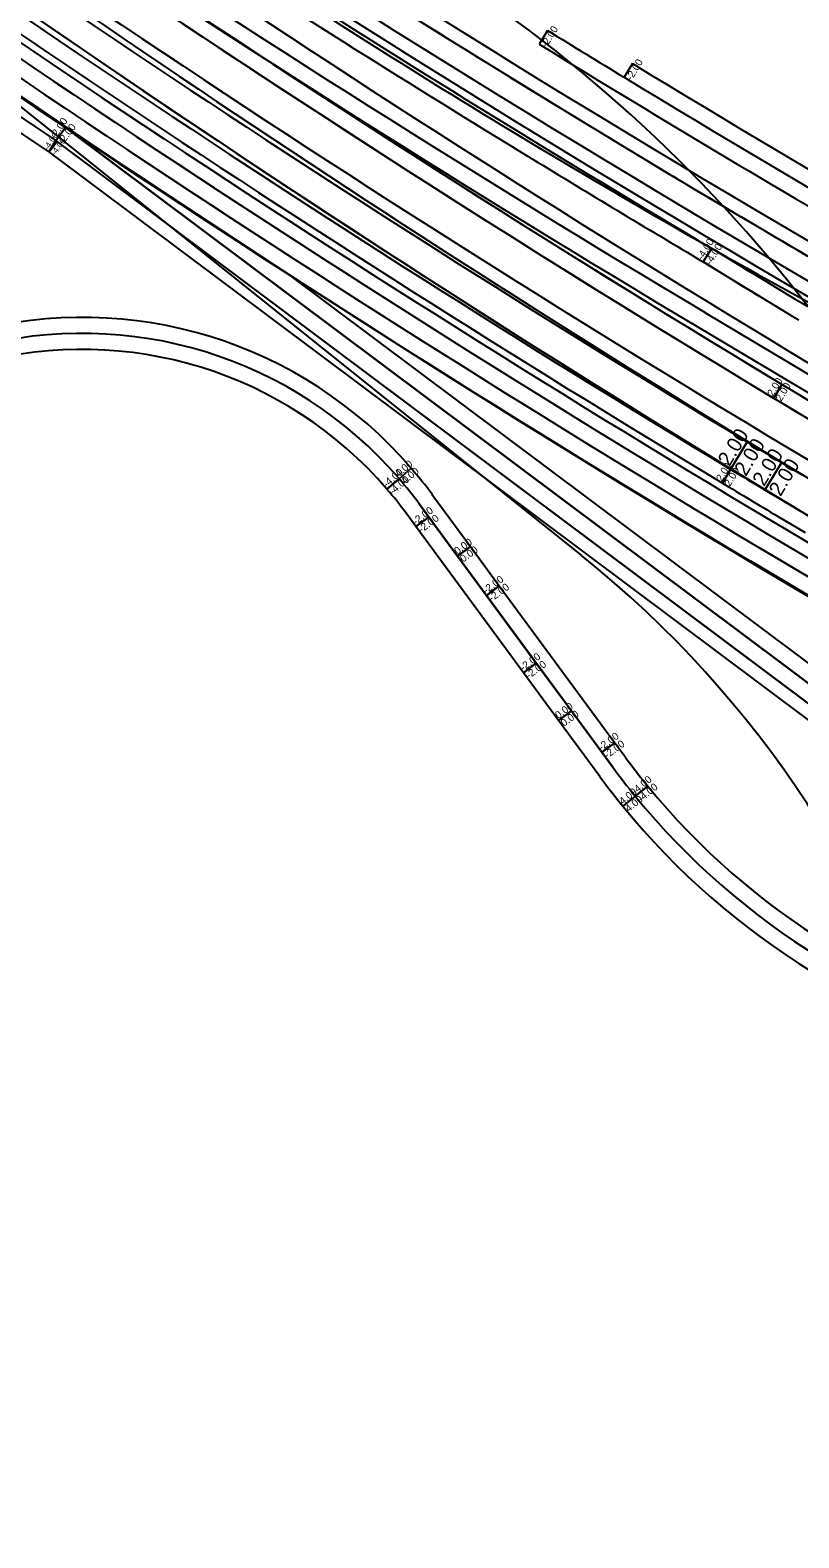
# Model space of a CAD drawing. Extents: x 2342222 to 2351711, y 366548 to 372860.
# Drawn here: x 2345691 to 2346266, y 369068 to 370197 of the extents above; entities that cross this region are included whole.
import ezdxf

# ---------------------------------------------------------------- set-up
doc = ezdxf.new("R2010")
doc.units = 0
for name, color, linetype in [('RD_HC_Cl', 7, 'Continuous'), ('RD_PD_Final_LnLine', 7, 'Continuous'), ('RD_PD_PaveShd', 7, 'Continuous'), ('RD_PD_SuperShp_BL_EB_526', 7, 'Continuous'), ('RD_PD_SuperShp_BL_WB_526', 7, 'Continuous'), ('RD_PD_SuperShp_EB_526', 7, 'Continuous'), ('RD_PD_SuperShp_LINE-A', 7, 'Continuous'), ('RD_PD_SuperShp_Line-B', 7, 'Continuous'), ('RD_PD_SuperShp_REL_L-2118', 7, 'Continuous'), ('RD_PD_SuperShp_REL_L-2523', 7, 'Continuous'), ('RD_PD_SuperShp_REL_LINE-3', 7, 'Continuous'), ('RD_PD_SuperShp_WB_526', 7, 'Continuous')]:
    doc.layers.add(name, color=color, linetype=linetype)

msp = doc.modelspace()

# ---------------------------------------------------------------- linework, layer by layer
at = {"layer": 'RD_HC_Cl'}
msp.add_line((2345614.6, 370194.7), (2346103.4, 369803.5), dxfattribs=at)
msp.add_line((2345614.6, 370194.7), (2346103.4, 369803.5), dxfattribs=at)
for centre, radius, start, end in [((2349158.4, 375253.9), 6000, 236.19528, 241.60251), ((2349158.4, 375253.9), 6000, 236.19528, 241.60251), ((2345401.1, 369318.9), 1100, 337.175, 58.1352), ((2345401.1, 369318.9), 1100, 337.175, 58.1352), ((2345603.4, 369178.9), 800, 339.7746, 51.3248), ((2345603.4, 369178.9), 800, 339.7746, 51.3248)]:
    msp.add_arc(centre, radius, start, end, dxfattribs=at)
at = {"layer": 'RD_PD_Final_LnLine'}
msp.add_line((2346236.7, 369794.6), (2347945.2, 368775.3), dxfattribs=at)
msp.add_line((2346236.7, 369794.6), (2347945.2, 368775.3), dxfattribs=at)
msp.add_arc((2351872.8, 379241), 11000, 231.26372, 239.17851, dxfattribs=at)
msp.add_arc((2351872.8, 379241), 11000, 231.26372, 239.17851, dxfattribs=at)
at = {"layer": 'RD_PD_PaveShd'}
for centre, radius, start, end in [((2352152.8, 379726.2), 11446, 233.26372, 239.17851), ((2352002, 379817.2), 11374.2, 235.48286, 239.33461), ((2352152.8, 379726.2), 11374.2, 238.44698, 238.8683), ((2352152.8, 379726.2), 11386.2, 238.44699, 238.8683)]:
    msp.add_arc(centre, radius, start, end, dxfattribs=at)
at = {"layer": 'RD_PD_SuperShp_BL_EB_526'}
for p, q in [((2346227.5, 369888.5), (2346215.1, 369867.9)), ((2346215.1, 369867.9), (2346227.5, 369888.5)), ((2346215.1, 369867.9), (2346208.9, 369857.7)), ((2346208.9, 369857.7), (2346215.1, 369867.9)), ((2346277, 369830.9), (2346256.4, 369843.2)), ((2346277, 369830.9), (2346256.4, 369843.2)), ((2346250.2, 369832.9), (2346270.8, 369820.6))]:
    msp.add_line(p, q, dxfattribs=at)
for radius, start, end in [(11472.3, 233.26372, 239.17851), (11484.3, 233.50318, 238.93904), (11484.3, 233.50318, 238.93904), (11508.3, 233.50318, 238.93904), (11508.3, 233.50318, 238.93904), (11520.3, 233.50318, 238.93904), (11484.3, 238.93904, 239.17851), (11484.3, 238.93904, 239.17851), (11508.3, 238.93904, 239.17851), (11508.3, 238.93904, 239.17851), (11520.3, 238.93904, 239.17851)]:
    msp.add_arc((2352152.8, 379726.2), radius, start, end, dxfattribs=at)
at = {"layer": 'RD_PD_SuperShp_BL_WB_526'}
for p, q in [((2346200.9, 370033.6), (2346194.6, 370023.4)), ((2346194.6, 370023.4), (2346200.9, 370033.6)), ((2346247.3, 369921.3), (2346253.5, 369931.6)), ((2346253.5, 369931.6), (2346247.3, 369921.3))]:
    msp.add_line(p, q, dxfattribs=at)
for centre, radius, start, end in [((2352152.8, 379726.2), 11410, 233.26372, 239.17851), ((2352152.8, 379726.2), 11434, 233.26372, 239.17851), ((2352152.8, 379726.2), 11434, 233.50319, 238.93903), ((2352152.8, 379726.2), 11446, 233.50319, 238.93903), ((2352002, 379817.2), 11374.2, 235.48286, 239.33461), ((2352002, 379817.2), 11386.2, 235.48286, 238.5668), ((2352002, 379817.2), 11386.2, 238.5668, 238.58075), ((2352002, 379817.2), 11386.2, 238.58075, 239.33369), ((2352152.8, 379726.2), 11374.2, 238.44699, 238.8683), ((2352152.8, 379726.2), 11386.2, 238.44699, 238.44792), ((2352152.8, 379726.2), 11386.2, 238.44792, 238.8683), ((2352152.8, 379726.2), 11434, 238.93903, 239.17851), ((2352152.8, 379726.2), 11446, 238.93903, 239.17851)]:
    msp.add_arc(centre, radius, start, end, dxfattribs=at)
at = {"layer": 'RD_PD_SuperShp_EB_526'}
for p, q in [((2346241, 369852.8), (2346253.3, 369873.4)), ((2346253.3, 369873.4), (2346241, 369852.8))]:
    msp.add_line(p, q, dxfattribs=at)
for radius, start, end in [(11459.2, 233.34382, 238.69829), (11483.2, 233.26372, 239.17851), (11483.2, 233.34465, 238.6991), (11459.2, 238.69829, 239.17851), (11483.2, 238.6991, 239.17851)]:
    msp.add_arc((2352206.9, 379664.6), radius, start, end, dxfattribs=at)
at = {"layer": 'RD_PD_SuperShp_LINE-A'}
for radius, start, end in [(11400.7, 232.99132, 239.10724), (11390.7, 232.99132, 240.43629), (11416.7, 232.99132, 240.43659), (11416.7, 232.99132, 240.43659), (11426.7, 232.99132, 240.43659), (11400.7, 237.52398, 238.02654), (11400.7, 238.02654, 238.52911), (11400.7, 238.52911, 239.03167), (11400.7, 239.03167, 239.10724), (11400.7, 239.10724, 240.43629), (11400.7, 239.10724, 239.53424), (11400.7, 239.53424, 240.0368)]:
    msp.add_arc((2352034, 379865.6), radius, start, end, dxfattribs=at)
at = {"layer": 'RD_PD_SuperShp_Line-B'}
for p, q in [((2345709.9, 370114.3), (2345717.1, 370123.9)), ((2345717.1, 370123.9), (2346489.7, 369545.7)), ((2345717.1, 370123.9), (2345882.8, 370014.8)), ((2346489.7, 369545.7), (2345717.1, 370123.9)), ((2345710.9, 370113.5), (2345704.9, 370105.5)), ((2345704.9, 370105.5), (2346273.6, 369679.9)), ((2346482.5, 369536.1), (2345709.9, 370114.3)), ((2346279.6, 369687.9), (2345710.9, 370113.5))]:
    msp.add_line(p, q, dxfattribs=at)
msp.add_lwpolyline([(2345882.8, 370014.8), (2346496.9, 369555.3)], dxfattribs=at)
at = {"layer": 'RD_PD_SuperShp_REL_L-2118'}
for p, q in [((2345976, 369868.8), (2345966.9, 369861)), ((2345966.9, 369861), (2345976, 369868.8)), ((2345966.9, 369861), (2345957.8, 369853.1)), ((2345957.8, 369853.1), (2345966.9, 369861)), ((2345991.5, 369849.3), (2346020.4, 369810.1)), ((2345979.5, 369825.1), (2345972.2, 369835.1)), ((2346010.7, 369802.9), (2345981.9, 369842.2)), ((2345981.9, 369842.2), (2345989.2, 369832.2)), ((2345989.2, 369832.2), (2345979.5, 369825.1)), ((2345979.5, 369825.1), (2345989.2, 369832.2)), ((2346060, 369715.7), (2345979.5, 369825.1)), ((2345989.2, 369832.2), (2346069.6, 369722.8)), ((2346020.4, 369810.1), (2346010.7, 369802.9)), ((2346010.7, 369802.9), (2346020.4, 369810.1)), ((2346032.3, 369773.6), (2346010.7, 369802.9)), ((2346020.4, 369810.1), (2346041.9, 369780.8)), ((2346041.9, 369780.8), (2346032.3, 369773.6)), ((2346032.3, 369773.6), (2346041.9, 369780.8)), ((2346041.9, 369780.8), (2346128.3, 369663.3)), ((2346118.6, 369656.2), (2346032.3, 369773.6)), ((2346069.6, 369722.8), (2346060, 369715.7)), ((2346060, 369715.7), (2346069.6, 369722.8)), ((2346069.6, 369722.8), (2346095.9, 369687.1)), ((2346086.2, 369680), (2346060, 369715.7)), ((2346095.9, 369687.1), (2346086.2, 369680)), ((2346086.2, 369680), (2346095.9, 369687.1)), ((2346095.9, 369687.1), (2346126.8, 369645)), ((2346117.2, 369637.9), (2346086.2, 369680)), ((2346128.3, 369663.3), (2346118.6, 369656.2)), ((2346118.6, 369656.2), (2346128.3, 369663.3)), ((2346126.8, 369645), (2346118.6, 369656.2)), ((2346128.3, 369663.3), (2346136.5, 369652.2)), ((2346153, 369630.8), (2346143.7, 369623.3)), ((2346143.7, 369623.3), (2346153, 369630.8)), ((2346143.7, 369623.3), (2346134.4, 369615.7)), ((2346143.7, 369623.3), (2346134.4, 369615.7))]:
    msp.add_line(p, q, dxfattribs=at)
for centre, radius, start, end in [((2345729.7, 369656.8), 325, 40.7245, 104.9909), ((2345729.7, 369656.8), 313, 40.7245, 104.9909), ((2345729.7, 369656.8), 313, 40.7245, 104.9909), ((2345729.7, 369656.8), 301, 40.7245, 104.9909), ((2345729.7, 369656.8), 325, 36.3291, 40.7245), ((2345729.7, 369656.8), 313, 36.3291, 40.7245), ((2345729.7, 369656.8), 313, 36.3291, 40.7245), ((2345729.7, 369656.8), 301, 36.3291, 40.7245), ((2346569.9, 369970.9), 550, 216.3291, 219.2013), ((2346569.9, 369970.9), 550, 216.3291, 219.2013), ((2346569.9, 369970.9), 538, 216.3291, 219.2013), ((2346569.9, 369970.9), 562, 216.3291, 219.2013), ((2346569.9, 369970.9), 538, 219.2013, 257.7603), ((2346569.9, 369970.9), 550, 219.2013, 257.7603), ((2346569.9, 369970.9), 550, 219.2013, 257.7603), ((2346569.9, 369970.9), 562, 219.2013, 257.7603)]:
    msp.add_arc(centre, radius, start, end, dxfattribs=at)
at = {"layer": 'RD_PD_SuperShp_REL_L-2523'}
for p, q in [((2346078, 370196.6), (2346071.7, 370186.4)), ((2346141.5, 370171.8), (2346135.3, 370161.6))]:
    msp.add_line(p, q, dxfattribs=at)
for radius, start, end in [(11356.2, 238.36761, 238.7063), (11368.2, 238.36761, 241.65529), (11356.2, 238.7063, 241.23779), (11356.2, 238.7063, 241.23779), (11344.2, 238.7063, 241.23779)]:
    msp.add_arc((2352034, 379865.6), radius, start, end, dxfattribs=at)
at = {"layer": 'RD_PD_SuperShp_REL_LINE-3'}
for p, q in [((2345710.1, 370114.1), (2345716.8, 370124)), ((2345704.4, 370105.9), (2345704.6, 370105.7)), ((2345704.6, 370105.7), (2345710.1, 370114.1)), ((2347921.7, 368829.6), (2346247.5, 369828.4)), ((2346242.4, 369819.8), (2347800.6, 368890.1)), ((2346242.4, 369819.8), (2347916.5, 368821)), ((2347794.5, 368879.8), (2346236.3, 369809.5)), ((2346236.3, 369809.5), (2347871.8, 368833.7)), ((2347865.6, 368823.4), (2346230.1, 369799.2))]:
    msp.add_line(p, q, dxfattribs=at)
for radius, start, end in [(11525.6, 233.26372, 239.17851), (11535.6, 233.26372, 239.17851), (11535.6, 233.26372, 239.17851), (11547.6, 233.26372, 239.17851), (11547.6, 233.26372, 239.17851), (11559.6, 233.26372, 239.17851), (11559.6, 233.26372, 236.16728), (11581.6, 233.26273, 236.16599), (11571.6, 233.26372, 236.16727), (11571.6, 233.26372, 236.16727)]:
    msp.add_arc((2352152.8, 379726.2), radius, start, end, dxfattribs=at)
at = {"layer": 'RD_PD_SuperShp_WB_526'}
msp.add_line((2346189.9, 369975), (2349293.2, 368123.5), dxfattribs=at)
msp.add_lwpolyline([(2349305.5, 368144.1), (2347116.8, 369450), (2347110.7, 369439.7), (2346196.1, 369985.3)], dxfattribs=at)
for radius in [11447.2, 11459.2]:
    msp.add_arc((2352061.2, 379815.8), radius, 233.26372, 239.17851, dxfattribs=at)

# ---------------------------------------------------------------- texts
at = {"layer": 'RD_PD_SuperShp_BL_EB_526'}
for height, p in [(11.04, (2346214.2, 369869.6)), (11.04, (2346226.5, 369862.2)), (5.52, (2346208.5, 369858.5)), (5.52, (2346214.6, 369854.8))]:
    msp.add_text('2.00', height=height, rotation=58.939, dxfattribs=at).set_placement(p)
at = {"layer": 'RD_PD_SuperShp_BL_WB_526'}
for s, rotation, p in [('-4.00', 58.4588, (2346194.1, 370024.2)), ('-4.00', 58.447, (2346200.3, 370020.5)), ('2.00', 58.939, (2346246.8, 369922.2)), ('2.00', 58.939, (2346253, 369918.5))]:
    msp.add_text(s, height=5.52, rotation=rotation, dxfattribs=at).set_placement(p)
at = {"layer": 'RD_PD_SuperShp_EB_526'}
for p in [(2346240.1, 369854.6), (2346252.4, 369847.1)]:
    msp.add_text('2.00', height=11.04, rotation=59.0882, dxfattribs=at).set_placement(p)
at = {"layer": 'RD_PD_SuperShp_Line-B'}
for s, height, p in [('-4.00', 4.6, (2345709.4, 370102.6)), ('-2.00', 5.52, (2345715.3, 370110.8))]:
    msp.add_text(s, height=height, rotation=53.1918, dxfattribs=at).set_placement(p)
at = {"layer": 'RD_PD_SuperShp_REL_L-2118'}
for s, rotation, p in [('-4.00', 40.7245, (2345957.6, 369854.1)), ('4.00', 40.7245, (2345966.7, 369861.9)), ('4.00', 40.7245, (2345971.4, 369856.5)), ('-4.00', 40.7245, (2345962.3, 369848.6)), ('-2.00', 36.3291, (2345979.4, 369826.1)), ('-2.00', 36.3291, (2345983.7, 369820.3)), ('0.00', 36.3291, (2346010.6, 369803.9)), ('0.00', 36.3291, (2346014.9, 369798.1)), ('-2.00', 36.3291, (2346032.1, 369774.6)), ('-2.00', 36.3291, (2346036.4, 369768.8)), ('-2.00', 36.3291, (2346059.8, 369716.7)), ('-2.00', 36.3291, (2346064.1, 369710.9)), ('0.00', 36.3291, (2346086.1, 369680.9)), ('0.00', 36.3291, (2346090.4, 369675.1)), ('-2.00', 36.3291, (2346118.5, 369657.1)), ('-2.00', 36.3291, (2346122.8, 369651.3)), ('-4.00', 39.2013, (2346143.6, 369624.2)), ('-4.00', 39.2013, (2346148.1, 369618.6)), ('4.00', 39.2013, (2346134.3, 369616.6)), ('4.00', 39.2013, (2346138.8, 369611))]:
    msp.add_text(s, height=5.52, rotation=rotation, dxfattribs=at).set_placement(p)
at = {"layer": 'RD_PD_SuperShp_REL_L-2523'}
for rotation, p in [(58.3676, (2346077.4, 370183.5)), (58.7063, (2346141, 370158.7))]:
    msp.add_text('-2.00', height=5.52, rotation=rotation, dxfattribs=at).set_placement(p)
at = {"layer": 'RD_PD_SuperShp_REL_LINE-3'}
for s, height, rotation, p in [('-2.00', 5.52, 56.1673, (2345709.7, 370114.9)), ('-4.00', 4.61, 56.1792, (2345704.2, 370106.5))]:
    msp.add_text(s, height=height, rotation=rotation, dxfattribs=at).set_placement(p)

doc.saveas('drawing.dxf')
